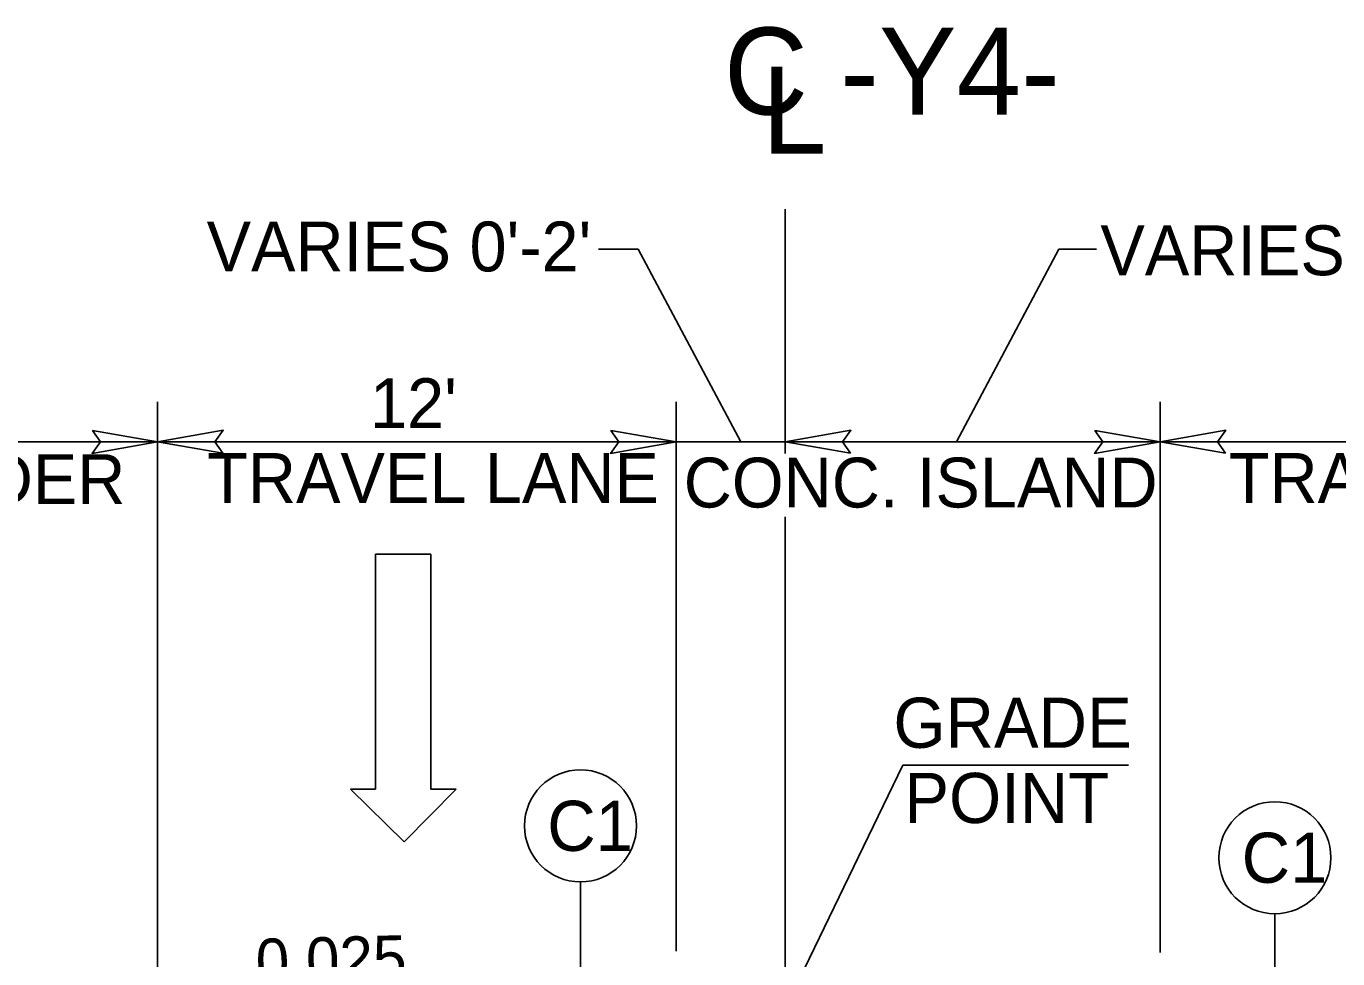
# Model space of a CAD drawing. Extents: x 2176156 to 2177167, y 76401 to 76644.
# Drawn here: x 2176304.2 to 2176334.56, y 76562.57 to 76584.15 of the extents above; entities that cross this region are included whole.
import ezdxf

# ---------------------------------------------------------------- set-up
doc = ezdxf.new("R2010")
doc.units = 0
for name, color, linetype in [('Exist Structure Minor Culvert Topo', 7, 'Continuous'), ('Exist Structure Minor Drop Inlet', 7, 'Continuous'), ('Exist Utilities Other Pole CELL', 7, 'Continuous'), ('Exist Vegetation Woods Line', 7, 'Continuous'), ('Old_Level_1', 7, 'Continuous'), ('Old_Level_3', 7, 'Continuous'), ('Prop North Arrow NAD83 for Plan Sheets CELL', 7, 'Continuous')]:
    doc.layers.add(name, color=color, linetype=linetype)

msp = doc.modelspace()

# ---------------------------------------------------------------- linework, layer by layer
at = {"layer": 'Exist Structure Minor Drop Inlet'}
for p, q in [((2176312.286, 76566.501), (2176312.286, 76571.933)), ((2176312.286, 76571.933), (2176313.566, 76571.933)), ((2176313.566, 76571.933), (2176313.566, 76566.501)), ((2176312.945, 76565.279), (2176311.704, 76566.501)), ((2176311.704, 76566.501), (2176312.286, 76566.501)), ((2176314.148, 76566.501), (2176312.945, 76565.279)), ((2176313.566, 76566.501), (2176314.148, 76566.501))]:
    msp.add_line(p, q, dxfattribs=at)
at = {"layer": 'Old_Level_1'}
for points in [[(2176305.729, 76574.795), (2176307.239, 76574.535), (2176305.721, 76574.267), (2176305.914, 76574.535)], [(2176308.749, 76574.275), (2176307.239, 76574.535), (2176308.757, 76574.803), (2176308.564, 76574.535)], [(2176317.729, 76574.795), (2176319.239, 76574.535), (2176317.721, 76574.267), (2176317.914, 76574.535)], [(2176323.279, 76574.275), (2176321.769, 76574.535), (2176323.287, 76574.803), (2176323.094, 76574.535)], [(2176328.934, 76574.795), (2176330.444, 76574.535), (2176328.926, 76574.267), (2176329.119, 76574.535)], [(2176331.954, 76574.275), (2176330.444, 76574.535), (2176331.962, 76574.803), (2176331.769, 76574.535)]]:
    msp.add_lwpolyline(points, close=True, dxfattribs=at)
at = {"layer": 'Old_Level_3'}
for p, q in [((2176321.769, 76575.333), (2176321.769, 76579.918)), ((2176318.365, 76578.995), (2176317.442, 76578.995)), ((2176320.739, 76574.535), (2176318.365, 76578.995)), ((2176325.729, 76574.535), (2176328.103, 76578.995)), ((2176328.103, 76578.995), (2176328.968, 76578.995)), ((2176307.239, 76562.277), (2176307.239, 76575.463)), ((2176319.239, 76562.747), (2176319.239, 76575.463)), ((2176321.769, 76574.261), (2176321.769, 76575.333)), ((2176330.444, 76562.798), (2176330.444, 76575.463)), ((2176330.444, 76562.722), (2176330.444, 76575.419)), ((2176307.239, 76574.535), (2176297.239, 76574.535)), ((2176319.239, 76574.535), (2176307.345, 76574.535)), ((2176330.444, 76574.535), (2176319.239, 76574.535)), ((2176342.444, 76574.535), (2176330.444, 76574.535)), ((2176321.769, 76553.503), (2176321.769, 76572.796))]:
    msp.add_line(p, q, dxfattribs=at)
at = {"layer": 'Prop North Arrow NAD83 for Plan Sheets CELL'}
for p, q in [((2176324.492, 76567.05), (2176321.769, 76561.442)), ((2176329.711, 76567.05), (2176324.492, 76567.05)), ((2176317.028, 76564.354), (2176317.028, 76561.221)), ((2176333.1, 76563.616), (2176333.1, 76560.812))]:
    msp.add_line(p, q, dxfattribs=at)
for centre in [(2176317.028, 76565.65), (2176333.1, 76564.912)]:
    msp.add_circle(centre, 1.296, dxfattribs=at)

# ---------------------------------------------------------------- texts
at = {"layer": 'Exist Structure Minor Culvert Topo'}
for s, height, p in [("VARIES 0'-2'", 1.15334, (2176308.374, 76578.477)), ("VARIES 0'-23'", 1.15334, (2176329.062, 76578.388)), ("12'", 1.1533, (2176312.157, 76574.851)), ('SHOULDER', 1.1533, (2176297.925, 76573.094)), ('TRAVEL LANE', 1.15334, (2176308.388, 76573.121)), ('CONC. ISLAND', 1.15334, (2176319.417, 76573.015)), ('TRAVEL LANE', 1.15334, (2176332.035, 76573.121))]:
    msp.add_text(s, height=height, dxfattribs=at).set_placement(p)
at = {"layer": 'Exist Utilities Other Pole CELL'}
msp.add_text('0.025', height=1.0429, rotation=1.4932, dxfattribs=at).set_placement((2176309.525, 76561.99))
at = {"layer": 'Exist Vegetation Woods Line'}
msp.add_text('C -Y4-', height=2.0131, dxfattribs=at).set_placement((2176320.348, 76582.106))
msp.add_text('L', height=2.013, rotation=359.9469, dxfattribs=at).set_placement((2176321.226, 76581.205))
at = {"layer": 'Prop North Arrow NAD83 for Plan Sheets CELL'}
for s, rotation, p in [('GRADE', 0.0002, (2176324.271, 76567.455)), ('POINT', 0.0002, (2176324.524, 76565.715)), ('C1', 0.0003, (2176316.259, 76565.07)), ('C1', 0.0003, (2176332.332, 76564.332))]:
    msp.add_text(s, height=1.16, rotation=rotation, dxfattribs=at).set_placement(p)

doc.saveas('drawing.dxf')
